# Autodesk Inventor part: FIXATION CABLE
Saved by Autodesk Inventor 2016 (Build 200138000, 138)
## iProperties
Created: 2013-10
Part Number: FIXATION CABLE
Material: Générique
Document SubType Name: Modeling
Designer: Bruno
Density: 1 g/cm^3
Appearance: Par défaut
Author: Bruno
Sending System: SolidWorks 2013
Last Author: christophe
Last Saved: 2014-02-15
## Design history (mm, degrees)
feature "Boss.-Extru.1"
node "Solide1"
